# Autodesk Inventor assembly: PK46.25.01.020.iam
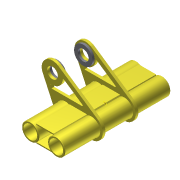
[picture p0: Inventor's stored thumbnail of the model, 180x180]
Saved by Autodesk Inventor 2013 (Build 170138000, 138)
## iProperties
Created: 2012-04
Part Number: PK46.25.01.020.iam
Document SubType Name: Assembly
Designer: Dale
Author: Designer 13
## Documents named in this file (7)
- C:\Product Design Suite 2013 Test Drive\Inventor to Showcase\Workspace\Assy, Chassis, Front\PK46.25.01.020.iam
- C:\Product Design Suite 2013 Test Drive\Inventor to Showcase\Workspace\Assy, Chassis, Front\PK46.25.01.005.ipt
- C:\Product Design Suite 2013 Test Drive\Inventor to Showcase\Workspace\Assy, Chassis, Front\PK46.25.01.006.ipt
- C:\Product Design Suite 2013 Test Drive\Inventor to Showcase\Workspace\Assy, Chassis, Front\PK46.25.01.007.ipt
- C:\Product Design Suite 2013 Test Drive\Inventor to Showcase\Workspace\Assy, Chassis, Front\PK46.25.01.009.ipt
- C:\Product Design Suite 2013 Test Drive\Inventor to Showcase\Workspace\Assy, Chassis, Front\PK46.25.01.009-01.ipt
- C:\Product Design Suite 2013 Test Drive\Inventor to Showcase\Workspace\Assy, Chassis, Front\PK46.25.01.016.ipt
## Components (12 placed, 6 different names)
1. PK46.25.01.005:1
2. PK46.25.01.005:2
3. PK46.25.01.006:1
4. PK46.25.01.006:2
5. PK46.25.01.007:1
6. PK46.25.01.007:2
7. PK46.25.01.009:1
8. PK46.25.01.009-01:1
9. PK46.25.01.009-01:2
10. PK46.25.01.009-01:3
11. PK46.25.01.009-01:4
12. PK46.25.01.016:1
## Named parameters: d5_d12 = 0, d6_d15 = 0, d7_d18 = 0
